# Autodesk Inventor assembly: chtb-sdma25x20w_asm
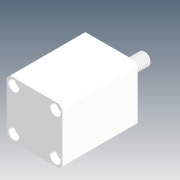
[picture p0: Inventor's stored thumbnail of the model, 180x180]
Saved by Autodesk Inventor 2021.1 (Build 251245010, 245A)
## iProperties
Company: Microsoft
Created: 2018-05
Part Number: chtb-sdma25x20w_asm
Description: STEP AP214
Document SubType Name: Assembly
Designer: user
Title: chtb-sdma25x20w_asm.STEP
Author: Windows
Revision Number: ÈÎºÎ
Sending System: SolidWorks 2015
Preprocessor: SwSTEP 2.0
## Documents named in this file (4)
- D:\Vault_2016\Projekty\Clamptek\Hydraulic\CHTB\CHTB-25\Inventor\chtb-sdma25x20w\chtb-sdma25x20w_asm.iam
- D:\Vault_2016\Projekty\Clamptek\Hydraulic\CHTB\CHTB-25\Inventor\chtb-sdma25x20w\CHTB-25QG.ipt
- D:\Vault_2016\Projekty\Clamptek\Hydraulic\CHTB\CHTB-25\Inventor\chtb-sdma25x20w\CHTB-SDMA25X20NBT.ipt
- D:\Vault_2016\Projekty\Clamptek\Hydraulic\CHTB\CHTB-25\Inventor\chtb-sdma25x20w\CHTB-SDMA25X20WHSG.ipt
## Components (3 placed, 3 different names)
1. CHTB-25QG_1
2. CHTB-SDMA25X20NBT_2
3. CHTB-SDMA25X20WHSG_3
